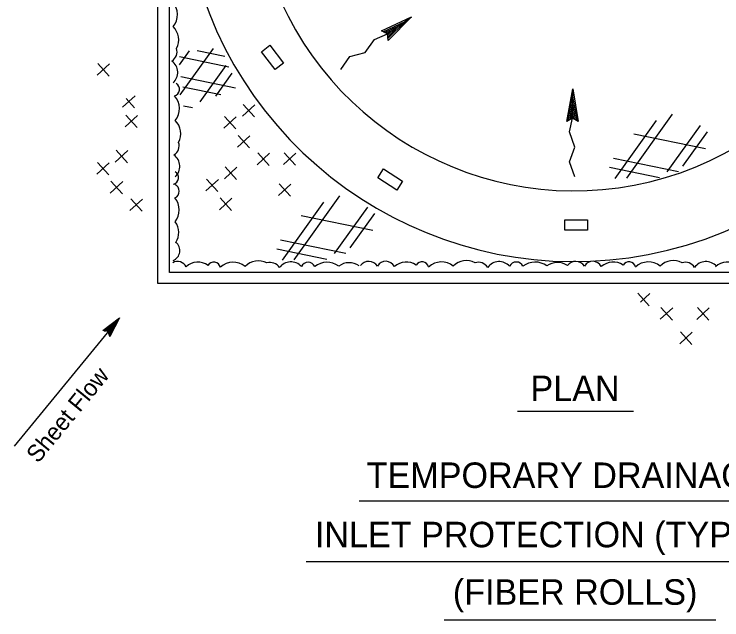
# Model space of a CAD drawing. Extents: x 6708945 to 6710368, y 1871409 to 1872338.
# Drawn here: x 6708985.5 to 6709235.1, y 1871409.4 to 1871623 of the extents above; entities that cross this region are included whole.
import ezdxf

# ---------------------------------------------------------------- set-up
doc = ezdxf.new("R2010")
doc.units = 0
for name, color, linetype in [('1 Control', 7, 'Continuous'), ('57 Undefined', 7, 'Continuous'), ('60 Nongeo Data', 7, 'Continuous'), ('62 As-Built Chng', 7, 'Continuous'), ('63 Undefined', 7, 'Continuous')]:
    doc.layers.add(name, color=color, linetype=linetype)

msp = doc.modelspace()

# ---------------------------------------------------------------- linework, layer by layer
at = {"layer": '1 Control'}
for p, q in [((6709022.59, 1871515.93), (6709022.59, 1871515.93)), ((6709016.78, 1871511.38), (6709016.78, 1871511.38)), ((6709019.26, 1871509.35), (6709019.26, 1871509.35))]:
    msp.add_line(p, q, dxfattribs=at)
msp.add_lwpolyline([(6709016.78, 1871511.38), (6709022.59, 1871515.93), (6709019.26, 1871509.35), (6709019.09, 1871509.82), (6709021.53, 1871514.64), (6709017.27, 1871511.31), (6709017.76, 1871511.24), (6709020.48, 1871513.37), (6709018.92, 1871510.29), (6709018.76, 1871510.76), (6709019.43, 1871512.09), (6709018.25, 1871511.16), (6709018.63, 1871511.11), (6709019.26, 1871509.35), (6709018.63, 1871511.11)], close=True, dxfattribs=at)
at = {"layer": '57 Undefined'}
for p, q in [((6709022.59, 1871515.93), (6708985.49, 1871470.65)), ((6709162.99, 1871482.99), (6709203.94, 1871482.99)), ((6709107.16, 1871451.4), (6709262.36, 1871451.4)), ((6709088.47, 1871429.96), (6709282.38, 1871429.96)), ((6709137.2, 1871409.38), (6709232.99, 1871409.38))]:
    msp.add_line(p, q, dxfattribs=at)
at = {"layer": '60 Nongeo Data'}
msp.add_arc((6709182.99, 1871674.08), 113.4, 20.4401, 11.3417, dxfattribs=at)
at = {"layer": '62 As-Built Chng'}
for p, q in [((6709014.75, 1871601.4), (6709019.15, 1871605.42)), ((6709015, 1871605.55), (6709019.02, 1871601.15)), ((6709023.72, 1871590.17), (6709028.12, 1871594.19)), ((6709024.99, 1871593.2), (6709027.99, 1871589.92)), ((6709065.99, 1871587), (6709070.39, 1871591.02)), ((6709066.24, 1871591.15), (6709070.26, 1871586.75)), ((6709024.9, 1871587.34), (6709028.92, 1871582.95)), ((6709024.65, 1871583.2), (6709029.05, 1871587.22)), ((6709059.42, 1871582.75), (6709063.81, 1871586.77)), ((6709059.66, 1871586.89), (6709063.68, 1871582.49)), ((6709064.21, 1871576.07), (6709068.6, 1871580.09)), ((6709064.46, 1871580.21), (6709068.48, 1871575.81)), ((6709021.17, 1871570.82), (6709025.57, 1871574.84)), ((6709021.42, 1871574.96), (6709025.44, 1871570.56)), ((6709071.17, 1871569.88), (6709075.57, 1871573.9)), ((6709071.42, 1871574.02), (6709075.44, 1871569.62)), ((6709080.45, 1871569.96), (6709084.85, 1871573.98)), ((6709080.7, 1871574.1), (6709084.72, 1871569.71)), ((6709014.6, 1871566.56), (6709019, 1871570.58)), ((6709014.85, 1871570.71), (6709018.87, 1871566.31)), ((6709059.69, 1871564.94), (6709064.09, 1871568.96)), ((6709059.94, 1871569.09), (6709063.96, 1871564.69)), ((6709053.36, 1871564.83), (6709057.38, 1871560.44)), ((6709019.39, 1871559.88), (6709023.79, 1871563.9)), ((6709019.64, 1871564.03), (6709023.66, 1871559.63)), ((6709053.12, 1871560.69), (6709057.51, 1871564.71)), ((6709078.67, 1871559.02), (6709083.07, 1871563.04)), ((6709078.92, 1871563.17), (6709082.94, 1871558.77)), ((6709026.35, 1871553.69), (6709030.75, 1871557.71)), ((6709026.6, 1871557.84), (6709030.62, 1871553.44)), ((6709057.91, 1871554.01), (6709062.3, 1871558.03)), ((6709058.16, 1871558.15), (6709062.18, 1871553.75)), ((6709205.5, 1871524.54), (6709209.52, 1871520.14)), ((6709206.37, 1871521.42), (6709209.65, 1871524.42)), ((6709213.37, 1871515.37), (6709217.77, 1871519.39)), ((6709213.62, 1871519.51), (6709217.64, 1871515.11)), ((6709226.25, 1871515.34), (6709230.64, 1871519.36)), ((6709226.5, 1871519.48), (6709230.52, 1871515.08)), ((6709220.24, 1871506.77), (6709224.64, 1871510.79)), ((6709220.49, 1871510.92), (6709224.51, 1871506.52))]:
    msp.add_line(p, q, dxfattribs=at)
for points in [[(6709036.13, 1871820.42), (6709330.46, 1871820.42), (6709330.46, 1871528.03), (6709036.13, 1871528.03)], [(6709040.24, 1871816.63), (6709326.68, 1871816.63), (6709326.68, 1871531.81), (6709040.24, 1871531.81)], [(6709072.73, 1871609.72), (6709075.65, 1871611.98), (6709080.51, 1871605.69), (6709077.59, 1871603.43)], [(6709113.77, 1871565.29), (6709115.79, 1871568.38), (6709122.45, 1871564.04), (6709120.43, 1871560.95)], [(6709179.72, 1871546.79), (6709179.72, 1871550.48), (6709187.67, 1871550.48), (6709187.67, 1871546.79)]]:
    msp.add_lwpolyline(points, close=True, dxfattribs=at)
msp.add_arc((6709182.99, 1871674.08), 138.36, 19.738, 11.782, dxfattribs=at)
at = {"layer": '63 Undefined'}
for p, q in [((6709115.05, 1871617.05), (6709125.68, 1871621.97)), ((6709115.61, 1871616.79), (6709123.42, 1871620.4)), ((6709123.42, 1871620.4), (6709117.32, 1871614.33)), ((6709125.68, 1871621.97), (6709117.37, 1871613.71)), ((6709116.19, 1871616.53), (6709121.17, 1871618.83)), ((6709116.76, 1871616.26), (6709118.87, 1871617.23)), ((6709118.87, 1871617.23), (6709117.22, 1871615.59)), ((6709121.17, 1871618.83), (6709117.27, 1871614.96)), ((6709117.18, 1871616.06), (6709115.05, 1871617.05)), ((6709117.37, 1871613.71), (6709117.18, 1871616.06)), ((6709047.22, 1871610.09), (6709043.64, 1871605.09)), ((6709055.66, 1871610.81), (6709043.95, 1871594.47)), ((6709050, 1871610.21), (6709059.82, 1871608.2)), ((6709043.85, 1871608), (6709061.24, 1871604.43)), ((6709060.14, 1871604.81), (6709050.97, 1871592.02)), ((6709044.25, 1871600.95), (6709063.58, 1871596.99)), ((6709062.25, 1871602.13), (6709056.46, 1871594.05)), ((6709044.95, 1871597.38), (6709058.33, 1871594.63)), ((6709180.37, 1871585.17), (6709182.5, 1871596.69)), ((6709182.5, 1871596.69), (6709184.44, 1871585.13)), ((6709180.91, 1871585.48), (6709182.48, 1871593.93)), ((6709182.48, 1871593.93), (6709183.91, 1871585.45)), ((6709045.24, 1871590.68), (6709048.35, 1871590.04)), ((6709181.46, 1871585.79), (6709182.46, 1871591.19)), ((6709182.46, 1871591.19), (6709183.36, 1871585.78)), ((6709182.01, 1871586.1), (6709182.43, 1871588.39)), ((6709182.43, 1871588.39), (6709182.82, 1871586.1)), ((6709217.62, 1871587.74), (6709201.45, 1871565.18)), ((6709182.42, 1871586.33), (6709180.37, 1871585.17)), ((6709184.44, 1871585.13), (6709182.42, 1871586.33)), ((6709211.99, 1871585.44), (6709197.33, 1871564.98)), ((6709227.44, 1871583.68), (6709215.74, 1871567.37)), ((6709204.09, 1871580.81), (6709229.38, 1871575.62)), ((6709229.91, 1871581.51), (6709221.23, 1871569.39)), ((6709196.84, 1871572.23), (6709219.85, 1871567.51)), ((6709195.45, 1871569.01), (6709213.12, 1871565.39)), ((6709100.27, 1871558.95), (6709084.09, 1871536.39)), ((6709094.64, 1871556.64), (6709079.97, 1871536.18)), ((6709110.08, 1871554.89), (6709098.38, 1871538.58)), ((6709112.56, 1871552.71), (6709103.87, 1871540.6)), ((6709086.73, 1871552.02), (6709112.02, 1871546.83)), ((6709079.48, 1871543.43), (6709102.5, 1871538.71)), ((6709078.1, 1871540.22), (6709095.76, 1871536.59))]:
    msp.add_line(p, q, dxfattribs=at)
for points in [[(6709100.67, 1871603.42), (6709103.92, 1871608), (6709109.35, 1871609.45), (6709112.6, 1871614.03), (6709117.18, 1871616.06), (6709125.68, 1871621.97)], [(6709183.2, 1871565.55), (6709181.34, 1871570.85), (6709183.28, 1871576.12), (6709181.42, 1871581.42), (6709182.42, 1871586.33), (6709182.5, 1871596.69)]]:
    msp.add_lwpolyline(points, dxfattribs=at)
for centre, radius, start, end in [((6709036.53, 1871622.78), 6.54, 319.9986, 43.3536), ((6709037.18, 1871613.93), 6.36, 331.3634, 46.8458), ((6709039.06, 1871609.72), 3.88, 302.3474, 17.3796), ((6709038.18, 1871602.41), 5, 312.1292, 53.705), ((6709041.42, 1871596.47), 2.4, 284.0578, 59.3233), ((6709037.25, 1871589.65), 6.54, 319.9986, 43.3536), ((6709037.91, 1871580.81), 6.36, 331.3634, 46.8458), ((6709039.79, 1871576.6), 3.88, 302.3474, 17.3796), ((6709038.9, 1871569.29), 5, 312.1292, 53.705), ((6709041.06, 1871565.34), 2.4, 284.0578, 59.3233), ((6709041.14, 1871560.52), 2.57, 294.5196, 65.4804), ((6709036.69, 1871553.87), 7, 323.3979, 37.9353), ((6709037.34, 1871546), 6.2, 325.656, 36.6973), ((6709040.26, 1871539.55), 3.68, 290.3255, 53.3403), ((6709043.13, 1871532.33), 3.41, 27.0211, 119.7865), ((6709050.32, 1871529.41), 6.1, 54.5002, 132.8354), ((6709055.92, 1871533.15), 2.4, 14.0578, 149.3233), ((6709062.74, 1871528.98), 6.54, 49.9986, 133.3536), ((6709071.58, 1871529.64), 6.36, 61.3634, 136.8458), ((6709075.79, 1871531.52), 3.88, 32.3474, 107.3796), ((6709083.1, 1871530.63), 5, 42.1292, 143.705), ((6709089.16, 1871532.92), 2.57, 24.5196, 155.4804), ((6709095.8, 1871528.47), 7, 53.3979, 127.9353), ((6709103.68, 1871529.12), 6.2, 55.656, 126.6973), ((6709110.58, 1871532.11), 3.68, 33.6905, 143.3403), ((6709116.57, 1871532.41), 3.41, 27.0211, 149.1913), ((6709123.75, 1871529.48), 6.1, 54.5002, 132.8354), ((6709129.36, 1871533.23), 2.4, 14.0578, 149.3233), ((6709136.17, 1871529.05), 6.54, 49.9986, 133.3536), ((6709145.02, 1871529.71), 6.36, 61.3634, 136.8458), ((6709149.23, 1871531.59), 3.88, 32.3474, 107.3796), ((6709156.54, 1871530.71), 5, 42.1292, 143.705), ((6709162.59, 1871532.99), 2.57, 24.5196, 155.4804), ((6709169.24, 1871528.54), 7, 53.3979, 127.9353), ((6709177.12, 1871529.19), 6.2, 55.656, 126.6973), ((6709183.56, 1871532.11), 3.68, 33.6905, 143.3403), ((6709189.55, 1871532.41), 3.41, 27.0211, 149.1913), ((6709196.74, 1871529.48), 6.1, 54.5002, 132.8354), ((6709202.34, 1871533.23), 2.4, 14.0578, 149.3233), ((6709209.16, 1871529.05), 6.54, 49.9986, 133.3536), ((6709218, 1871529.71), 6.36, 61.3634, 136.8458), ((6709222.21, 1871531.59), 3.88, 32.3474, 107.3796), ((6709229.52, 1871530.71), 5, 42.1292, 143.705), ((6709237.04, 1871529.41), 6.1, 54.5002, 132.8354)]:
    msp.add_arc(centre, radius, start, end, dxfattribs=at)

# ---------------------------------------------------------------- texts
at = {"layer": '57 Undefined'}
msp.add_text('Sheet Flow', height=6, rotation=50.6735, dxfattribs=at).set_placement((6708993.91, 1871464.31))
for s, p in [('PLAN', (6709167.6, 1871486.51)), ('TEMPORARY DRAINAGE', (6709109.83, 1871455.88)), ('INLET PROTECTION (TYPE 4A)', (6709091.56, 1871434.96)), ('(FIBER ROLLS)', (6709140.22, 1871414.7))]:
    msp.add_text(s, height=9, dxfattribs=at).set_placement(p)

doc.saveas('drawing.dxf')
